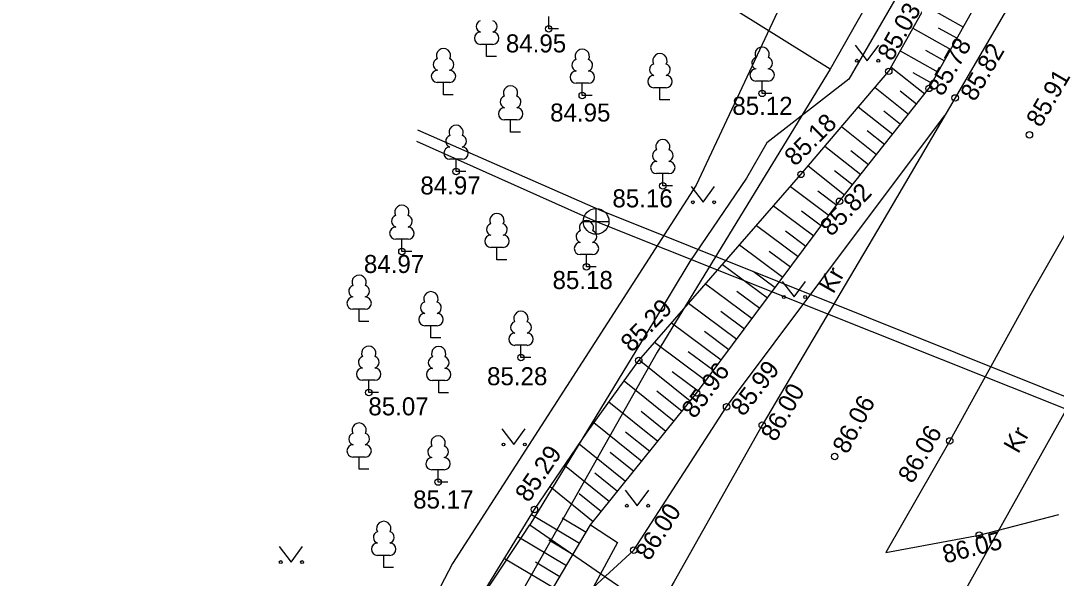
# Model space of a CAD drawing. Extents: x 648748 to 649126, y 6457789 to 6458252.
# Drawn here: x 648844.2 to 648884.43, y 6458119.64 to 6458141.27 of the extents above; entities that cross this region are included whole.
import ezdxf

# ---------------------------------------------------------------- set-up
doc = ezdxf.new("R2010")
doc.units = 0
for name, color, linetype in [('HALJASTUS', 7, 'Continuous'), ('KKAEV', 7, 'Continuous'), ('KORGUS-EH2000', 7, 'Continuous'), ('KTRASS', 7, 'Continuous'), ('PIIR', 7, 'Continuous'), ('PUU', 7, 'Continuous'), ('RELJEEF', 7, 'Continuous'), ('SITRASS', 7, 'Continuous'), ('TEE', 7, 'Continuous'), ('VTRASS', 7, 'Continuous')]:
    doc.layers.add(name, color=color, linetype=linetype)

msp = doc.modelspace()

# ---------------------------------------------------------------- linework, layer by layer
at = {"layer": 'HALJASTUS'}
for p, q in [((648876.62, 6458140.322), (648877.084, 6458139.716)), ((648877.084, 6458139.716), (648877.529, 6458140.322)), ((648870.245, 6458134.831), (648870.708, 6458134.225)), ((648870.708, 6458134.225), (648871.154, 6458134.831)), ((648873.781, 6458131.155), (648874.245, 6458130.549)), ((648874.245, 6458130.549), (648874.69, 6458131.155)), ((648862.892, 6458125.431), (648863.356, 6458124.825)), ((648863.356, 6458124.825), (648863.801, 6458125.431)), ((648867.685, 6458123.058), (648868.149, 6458122.451)), ((648868.149, 6458122.451), (648868.594, 6458123.058)), ((648854.237, 6458120.871), (648854.7, 6458120.264)), ((648854.7, 6458120.264), (648855.146, 6458120.871))]:
    msp.add_line(p, q, dxfattribs=at)
for centre in [(648876.683, 6458139.716), (648877.512, 6458139.716), (648870.307, 6458134.225), (648871.136, 6458134.225), (648873.844, 6458130.549), (648874.673, 6458130.549), (648862.955, 6458124.825), (648863.784, 6458124.825), (648867.748, 6458122.451), (648868.577, 6458122.451), (648854.299, 6458120.264), (648855.128, 6458120.264)]:
    msp.add_circle(centre, 0.055, dxfattribs=at)
at = {"layer": 'KKAEV'}
for p, q in [((648866.552, 6458132.983), (648866.552, 6458133.983)), ((648866.052, 6458133.483), (648867.052, 6458133.483))]:
    msp.add_line(p, q, dxfattribs=at)
msp.add_circle((648866.552, 6458133.483), 0.5, dxfattribs=at)
at = {"layer": 'KORGUS-EH2000'}
for centre in [(648864.71, 6458140.952), (648877.92, 6458139.306), (648879.482, 6458138.641), (648866.014, 6458138.367), (648873, 6458138.45), (648880.501, 6458138.274), (648883.385, 6458136.841), (648861.112, 6458135.416), (648874.51, 6458135.307), (648869.143, 6458134.861), (648876.009, 6458134.263), (648859.008, 6458132.315), (648866.176, 6458131.718), (648863.633, 6458128.199), (648868.207, 6458128.087), (648857.719, 6458126.844), (648870.456, 6458126.824), (648871.621, 6458126.287), (648873.007, 6458125.579), (648880.288, 6458124.965), (648875.819, 6458124.361), (648860.414, 6458123.369), (648864.155, 6458122.302), (648881.434, 6458121.312), (648868.014, 6458120.727)]:
    msp.add_circle(centre, 0.125, dxfattribs=at)
at = {"layer": 'KTRASS'}
for p, q in [((648859.569, 6458136.592), (648866.552, 6458133.483)), ((648866.552, 6458133.483), (648887.002, 6458125.324))]:
    msp.add_line(p, q, dxfattribs=at)
at = {"layer": 'PIIR'}
for p, q in [((648904.5, 6458190.31), (648875.65, 6458139.39)), ((648875.65, 6458139.39), (648850.168, 6458155.262)), ((648875.65, 6458139.39), (648868.92, 6458128.41)), ((648874.11, 6458107.05), (648886.69, 6458129.53)), ((648868.92, 6458128.41), (648793.25, 6457994.41))]:
    msp.add_line(p, q, dxfattribs=at)
at = {"layer": 'PUU'}
for p, q in [((648864.71, 6458140.952), (648864.71, 6458141.427)), ((648865.09, 6458140.952), (648864.71, 6458140.952)), ((648862.539, 6458140.351), (648862.059, 6458140.351)), ((648862.299, 6458139.876), (648862.299, 6458140.351)), ((648862.679, 6458139.876), (648862.299, 6458139.876)), ((648860.864, 6458138.872), (648860.384, 6458138.872)), ((648860.624, 6458138.397), (648860.624, 6458138.872)), ((648866.253, 6458138.842), (648865.774, 6458138.842)), ((648866.014, 6458138.367), (648866.014, 6458138.842)), ((648869.271, 6458138.671), (648868.791, 6458138.671)), ((648869.031, 6458138.196), (648869.031, 6458138.671)), ((648873.24, 6458138.925), (648872.76, 6458138.925)), ((648873, 6458138.45), (648873, 6458138.925)), ((648861.004, 6458138.397), (648860.624, 6458138.397)), ((648866.394, 6458138.367), (648866.014, 6458138.367)), ((648869.411, 6458138.196), (648869.031, 6458138.196)), ((648873.38, 6458138.45), (648873, 6458138.45)), ((648863.47, 6458137.419), (648862.99, 6458137.419)), ((648863.23, 6458136.944), (648863.23, 6458137.419)), ((648863.61, 6458136.944), (648863.23, 6458136.944)), ((648861.352, 6458135.891), (648860.872, 6458135.891)), ((648861.112, 6458135.416), (648861.112, 6458135.891)), ((648861.492, 6458135.416), (648861.112, 6458135.416)), ((648869.383, 6458135.336), (648868.903, 6458135.336)), ((648869.143, 6458134.861), (648869.143, 6458135.336)), ((648869.523, 6458134.861), (648869.143, 6458134.861)), ((648859.248, 6458132.79), (648858.768, 6458132.79)), ((648859.008, 6458132.315), (648859.008, 6458132.79)), ((648859.388, 6458132.315), (648859.008, 6458132.315)), ((648862.94, 6458132.472), (648862.46, 6458132.472)), ((648862.7, 6458131.997), (648862.7, 6458132.472)), ((648866.416, 6458132.193), (648865.936, 6458132.193)), ((648866.176, 6458131.718), (648866.176, 6458132.193)), ((648863.08, 6458131.997), (648862.7, 6458131.997)), ((648866.556, 6458131.718), (648866.176, 6458131.718)), ((648857.585, 6458130.076), (648857.105, 6458130.076)), ((648857.345, 6458129.601), (648857.345, 6458130.076)), ((648857.725, 6458129.601), (648857.345, 6458129.601)), ((648860.376, 6458129.435), (648859.896, 6458129.435)), ((648860.136, 6458128.96), (648860.136, 6458129.435)), ((648860.516, 6458128.96), (648860.136, 6458128.96)), ((648863.873, 6458128.674), (648863.393, 6458128.674)), ((648863.633, 6458128.199), (648863.633, 6458128.674)), ((648864.013, 6458128.199), (648863.633, 6458128.199)), ((648857.959, 6458127.319), (648857.479, 6458127.319)), ((648857.719, 6458126.844), (648857.719, 6458127.319)), ((648860.676, 6458127.306), (648860.196, 6458127.306)), ((648860.436, 6458126.831), (648860.436, 6458127.306)), ((648858.099, 6458126.844), (648857.719, 6458126.844)), ((648860.816, 6458126.831), (648860.436, 6458126.831)), ((648857.586, 6458124.34), (648857.106, 6458124.34)), ((648857.346, 6458123.865), (648857.346, 6458124.34)), ((648857.726, 6458123.865), (648857.346, 6458123.865)), ((648860.654, 6458123.844), (648860.174, 6458123.844)), ((648860.414, 6458123.369), (648860.414, 6458123.844)), ((648860.794, 6458123.369), (648860.414, 6458123.369)), ((648858.541, 6458120.525), (648858.061, 6458120.525)), ((648858.301, 6458120.05), (648858.301, 6458120.525)), ((648858.681, 6458120.05), (648858.301, 6458120.05))]:
    msp.add_line(p, q, dxfattribs=at)
for centre, radius, start, end in [((648862.129, 6458141.048), 0.233, 109.022, 253.142), ((648862.469, 6458141.048), 0.233, 286.851, 70.986), ((648862.062, 6458140.588), 0.238, 90.002, 269.395), ((648862.537, 6458140.588), 0.238, 270.605, 89.998), ((648873, 6458139.97), 0.277, 332.58, 207.42), ((648860.624, 6458139.917), 0.277, 332.58, 207.42), ((648866.014, 6458139.887), 0.277, 332.58, 207.42), ((648869.031, 6458139.716), 0.277, 332.58, 207.42), ((648872.83, 6458139.623), 0.233, 109.022, 253.142), ((648873.17, 6458139.623), 0.233, 286.851, 70.986), ((648860.454, 6458139.57), 0.233, 109.022, 253.142), ((648860.794, 6458139.57), 0.233, 286.851, 70.986), ((648865.844, 6458139.54), 0.233, 109.022, 253.142), ((648866.184, 6458139.54), 0.233, 286.851, 70.986), ((648868.861, 6458139.368), 0.233, 109.022, 253.142), ((648869.201, 6458139.368), 0.233, 286.851, 70.986), ((648860.386, 6458139.11), 0.238, 90.002, 269.395), ((648860.861, 6458139.11), 0.238, 270.605, 89.998), ((648865.776, 6458139.08), 0.238, 90.002, 269.395), ((648866.251, 6458139.08), 0.238, 270.605, 89.998), ((648868.794, 6458138.908), 0.238, 90.002, 269.395), ((648869.269, 6458138.908), 0.238, 270.605, 89.998), ((648872.763, 6458139.163), 0.238, 90.002, 269.395), ((648873.238, 6458139.163), 0.238, 270.605, 89.998), ((648863.23, 6458138.464), 0.277, 332.58, 207.42), ((648863.06, 6458138.117), 0.233, 109.022, 253.142), ((648863.4, 6458138.117), 0.233, 286.851, 70.986), ((648862.993, 6458137.657), 0.238, 90.002, 269.395), ((648863.468, 6458137.657), 0.238, 270.605, 89.998), ((648861.112, 6458136.936), 0.277, 332.58, 207.42), ((648860.942, 6458136.589), 0.233, 109.022, 253.142), ((648861.282, 6458136.589), 0.233, 286.851, 70.986), ((648869.143, 6458136.381), 0.277, 332.58, 207.42), ((648860.875, 6458136.129), 0.238, 90.002, 269.395), ((648861.35, 6458136.129), 0.238, 270.605, 89.998), ((648868.973, 6458136.033), 0.233, 109.022, 253.142), ((648869.313, 6458136.033), 0.233, 286.851, 70.986), ((648868.905, 6458135.573), 0.238, 90.002, 269.395), ((648869.38, 6458135.573), 0.238, 270.605, 89.998), ((648859.008, 6458133.835), 0.277, 332.58, 207.42), ((648862.7, 6458133.517), 0.277, 332.58, 207.42), ((648858.838, 6458133.487), 0.233, 109.022, 253.142), ((648859.178, 6458133.487), 0.233, 286.851, 70.986), ((648862.53, 6458133.17), 0.233, 109.022, 253.142), ((648862.87, 6458133.17), 0.233, 286.851, 70.986), ((648866.176, 6458133.238), 0.277, 332.58, 207.42), ((648858.77, 6458133.027), 0.238, 90.002, 269.395), ((648859.245, 6458133.027), 0.238, 270.605, 89.998), ((648866.006, 6458132.891), 0.233, 109.022, 253.142), ((648866.346, 6458132.891), 0.233, 286.851, 70.986), ((648862.462, 6458132.71), 0.238, 90.002, 269.395), ((648862.937, 6458132.71), 0.238, 270.605, 89.998), ((648865.939, 6458132.431), 0.238, 90.002, 269.395), ((648866.414, 6458132.431), 0.238, 270.605, 89.998), ((648857.345, 6458131.121), 0.277, 332.58, 207.42), ((648857.175, 6458130.773), 0.233, 109.022, 253.142), ((648857.515, 6458130.773), 0.233, 286.851, 70.986), ((648857.108, 6458130.313), 0.238, 90.002, 269.395), ((648857.583, 6458130.313), 0.238, 270.605, 89.998), ((648860.136, 6458130.48), 0.277, 332.58, 207.42), ((648859.966, 6458130.133), 0.233, 109.022, 253.142), ((648860.306, 6458130.133), 0.233, 286.851, 70.986), ((648859.898, 6458129.673), 0.238, 90.002, 269.395), ((648860.373, 6458129.673), 0.238, 270.605, 89.998), ((648863.633, 6458129.719), 0.277, 332.58, 207.42), ((648863.463, 6458129.371), 0.233, 109.022, 253.142), ((648863.803, 6458129.371), 0.233, 286.851, 70.986), ((648863.395, 6458128.911), 0.238, 90.002, 269.395), ((648863.87, 6458128.911), 0.238, 270.605, 89.998), ((648857.719, 6458128.364), 0.277, 332.58, 207.42), ((648860.436, 6458128.351), 0.277, 332.58, 207.42), ((648857.549, 6458128.016), 0.233, 109.022, 253.142), ((648857.889, 6458128.016), 0.233, 286.851, 70.986), ((648860.266, 6458128.004), 0.233, 109.022, 253.142), ((648860.606, 6458128.004), 0.233, 286.851, 70.986), ((648857.482, 6458127.556), 0.238, 90.002, 269.395), ((648857.957, 6458127.556), 0.238, 270.605, 89.998), ((648860.199, 6458127.544), 0.238, 90.002, 269.395), ((648860.674, 6458127.544), 0.238, 270.605, 89.998), ((648857.346, 6458125.385), 0.277, 332.58, 207.42), ((648857.176, 6458125.038), 0.233, 109.022, 253.142), ((648857.516, 6458125.038), 0.233, 286.851, 70.986), ((648860.414, 6458124.889), 0.277, 332.58, 207.42), ((648857.109, 6458124.578), 0.238, 90.002, 269.395), ((648857.584, 6458124.578), 0.238, 270.605, 89.998), ((648860.244, 6458124.541), 0.233, 109.022, 253.142), ((648860.584, 6458124.541), 0.233, 286.851, 70.986), ((648860.176, 6458124.081), 0.238, 90.002, 269.395), ((648860.651, 6458124.081), 0.238, 270.605, 89.998), ((648858.301, 6458121.57), 0.277, 332.58, 207.42), ((648858.131, 6458121.222), 0.233, 109.022, 253.142), ((648858.471, 6458121.222), 0.233, 286.851, 70.986), ((648858.064, 6458120.762), 0.238, 90.002, 269.395), ((648858.539, 6458120.762), 0.238, 270.605, 89.998)]:
    msp.add_arc(centre, radius, start, end, dxfattribs=at)
at = {"layer": 'RELJEEF'}
for p, q in [((648879.348, 6458141.848), (648880.819, 6458141.022)), ((648878.858, 6458140.976), (648880.329, 6458140.15)), ((648879.838, 6458140.999), (648880.574, 6458140.586)), ((648878.368, 6458140.104), (648879.84, 6458139.278)), ((648879.349, 6458140.127), (648880.084, 6458139.714)), ((648878.009, 6458139.465), (648879.315, 6458138.43)), ((648878.859, 6458139.255), (648879.595, 6458138.842)), ((648877.388, 6458138.682), (648878.693, 6458137.646)), ((648878.358, 6458138.55), (648879.004, 6458138.038)), ((648876.738, 6458137.921), (648878.072, 6458136.863)), ((648877.723, 6458137.778), (648878.382, 6458137.255)), ((648876.089, 6458137.159), (648877.45, 6458136.079)), ((648877.087, 6458137.006), (648877.761, 6458136.471)), ((648875.44, 6458136.398), (648876.829, 6458135.296)), ((648876.452, 6458136.233), (648877.139, 6458135.688)), ((648874.791, 6458135.636), (648876.207, 6458134.513)), ((648875.817, 6458135.461), (648876.518, 6458134.904)), ((648874.1, 6458134.838), (648875.602, 6458133.717)), ((648875.165, 6458134.667), (648875.901, 6458134.118)), ((648873.441, 6458134.082), (648875.003, 6458132.916)), ((648874.536, 6458133.888), (648875.302, 6458133.316)), ((648872.781, 6458133.327), (648874.405, 6458132.114)), ((648873.907, 6458133.11), (648874.704, 6458132.515)), ((648872.122, 6458132.571), (648873.807, 6458131.313)), ((648873.279, 6458132.331), (648874.106, 6458131.714)), ((648871.462, 6458131.816), (648873.209, 6458130.512)), ((648872.65, 6458131.553), (648873.508, 6458130.912)), ((648870.802, 6458131.06), (648872.61, 6458129.71)), ((648872.021, 6458130.775), (648872.909, 6458130.111)), ((648870.143, 6458130.305), (648872.012, 6458128.909)), ((648871.392, 6458129.996), (648872.311, 6458129.31)), ((648869.483, 6458129.549), (648871.414, 6458128.108)), ((648870.763, 6458129.218), (648871.713, 6458128.508)), ((648868.824, 6458128.794), (648870.816, 6458127.307)), ((648870.134, 6458128.439), (648871.115, 6458127.707)), ((648868.226, 6458128.109), (648870.206, 6458126.514)), ((648869.505, 6458127.661), (648870.516, 6458126.906)), ((648867.638, 6458127.298), (648869.579, 6458125.735)), ((648868.911, 6458126.914), (648869.892, 6458126.125)), ((648867.052, 6458126.486), (648868.951, 6458124.956)), ((648868.305, 6458126.119), (648869.265, 6458125.346)), ((648866.466, 6458125.674), (648868.324, 6458124.177)), ((648867.698, 6458125.323), (648868.638, 6458124.567)), ((648865.891, 6458124.853), (648867.697, 6458123.399)), ((648867.092, 6458124.528), (648868.011, 6458123.788)), ((648865.327, 6458124.023), (648867.07, 6458122.62)), ((648866.496, 6458123.724), (648867.384, 6458123.009)), ((648864.762, 6458123.194), (648866.443, 6458121.841)), ((648865.9, 6458122.919), (648866.756, 6458122.23)), ((648864.036, 6458122.108), (648865.913, 6458120.994)), ((648865.238, 6458121.976), (648866.168, 6458121.424)), ((648863.511, 6458121.256), (648865.403, 6458120.134)), ((648864.716, 6458121.123), (648865.658, 6458120.564)), ((648862.987, 6458120.405), (648864.893, 6458119.274)), ((648864.199, 6458120.267), (648865.148, 6458119.704))]:
    msp.add_line(p, q, dxfattribs=at)
for points in [[(648843.02, 6458077.359), (648843.42, 6458078.532), (648845.59, 6458084.371), (648850.065, 6458093.899), (648854.008, 6458102.777), (648855.882, 6458106.866), (648857.274, 6458110.27), (648859.944, 6458115.461), (648864.155, 6458122.302), (648866.203, 6458125.31), (648868.207, 6458128.087), (648874.51, 6458135.307), (648877.92, 6458139.306), (648882.178, 6458146.884)], [(648844.206, 6458076.8), (648844.687, 6458077.74), (648847.597, 6458083.411), (648851.411, 6458092.995), (648855.57, 6458101.941), (648857.624, 6458105.762), (648858.713, 6458108.175), (648859.587, 6458110.038), (648862.771, 6458115.697), (648866.339, 6458121.712), (648870.456, 6458126.824), (648876.009, 6458134.263), (648879.482, 6458138.641), (648881.386, 6458142.032), (648883.388, 6458145.778), (648883.683, 6458146.633)]]:
    msp.add_lwpolyline(points, dxfattribs=at)
at = {"layer": 'SITRASS'}
for points in [[(648929.925, 6458240.085), (648929.233, 6458238.833), (648926.729, 6458233.327), (648923.21, 6458225.506), (648918.966, 6458215.361), (648917.027, 6458210.342), (648911.341, 6458199.533), (648902.157, 6458183.584), (648896.992, 6458174.764), (648890.118, 6458163.377), (648888.523, 6458160), (648880.878, 6458146.779), (648876.372, 6458138.998), (648873.186, 6458136.533), (648872.398, 6458135.159), (648870.194, 6458131.921), (648868.778, 6458129.583), (648863.975, 6458121.708)], [(648896.343, 6458186.017), (648897.439, 6458185.494), (648891.994, 6458176.157), (648887.134, 6458166.562), (648880.865, 6458155.928), (648874.577, 6458143.726), (648870.442, 6458134.893), (648860.973, 6458120.207), (648854.483, 6458107.787), (648851.762, 6458098.853), (648850.917, 6458095.378), (648847.878, 6458090.581), (648844.467, 6458087.013), (648842.522, 6458085.072), (648840.521, 6458082.239)], [(648863.975, 6458121.708), (648868.963, 6458118.276), (648873.908, 6458114.787), (648879.921, 6458111.046), (648881.11, 6458110.63), (648883.242, 6458110.955), (648895.055, 6458116.596), (648901.713, 6458119.167), (648915.597, 6458124.69), (648933.55, 6458131.654), (648947.17, 6458136.394), (648958.488, 6458140.137), (648967.592, 6458140.769)], [(648840.642, 6458076.21), (648839.879, 6458076.526), (648839.144, 6458077.498), (648844.394, 6458087.729), (648849.387, 6458096.156), (648854.312, 6458104.237), (648857.262, 6458110.389), (648861.217, 6458117.552), (648863.683, 6458121.25), (648863.975, 6458121.708)]]:
    msp.add_lwpolyline(points, dxfattribs=at)
at = {"layer": 'TEE'}
for points in [[(648898.467, 6458156.964), (648883.402, 6458130.595), (648880.288, 6458124.965), (648877.804, 6458120.639), (648881.434, 6458121.312), (648884.526, 6458122.113)], [(648886.897, 6458149.241), (648880.501, 6458138.274), (648877.651, 6458133.428), (648873.007, 6458125.579), (648869.584, 6458119.515), (648862.268, 6458107.116), (648858.84, 6458100.574), (648853.992, 6458092.302), (648848.947, 6458082.671), (648845.759, 6458077.188), (648844.3, 6458074.59)], [(648866.432, 6458119.274), (648868.014, 6458120.727), (648871.621, 6458126.287), (648877.176, 6458133.694), (648880.102, 6458137.595)], [(648860.41, 6458108.819), (648859.531, 6458107.727), (648858.713, 6458108.175), (648859.587, 6458110.038), (648862.771, 6458115.697), (648866.339, 6458121.712), (648867.381, 6458121.025), (648866.432, 6458119.274)]]:
    msp.add_lwpolyline(points, dxfattribs=at)
at = {"layer": 'VTRASS'}
msp.add_lwpolyline([(648859.612, 6458137.039), (648866.748, 6458133.902), (648887.357, 6458125.656), (648899.553, 6458111.732), (648928.544, 6458121.558), (648956.932, 6458132.595), (648957.558, 6458132.798), (648975.434, 6458138.594), (648975.797, 6458138.798), (648976.302, 6458139.082)], dxfattribs=at)

# ---------------------------------------------------------------- texts
at = {"layer": 'KORGUS-EH2000'}
for s, rotation, p in [('85.03', 60.668, (648878.046, 6458139.662)), ('85.78', 60.6928, (648880.008, 6458138.302)), ('85.82', 59.7476, (648881.262, 6458138.098)), ('85.91', 59.7476, (648883.819, 6458137.091)), ('85.18', 44.5787, (648874.281, 6458135.59)), ('85.82', 46.0675, (648875.687, 6458132.866)), ('85.29', 46.0649, (648867.936, 6458128.37)), ('85.96', 53.427, (648870.377, 6458125.791)), ('85.99', 52.0503, (648872.273, 6458125.881)), ('86.00', 60.3537, (648873.52, 6458124.894)), ('86.06', 61.9984, (648876.312, 6458124.418)), ('86.06', 60.1394, (648878.844, 6458123.274)), ('85.29', 55.8044, (648863.932, 6458122.54)), ('86.00', 57.3647, (648868.62, 6458120.275)), ('86.05', 14.5247, (648880.111, 6458120.206))]:
    msp.add_text(s, height=0.7, rotation=rotation, dxfattribs=at).set_placement(p)
for s, p in [('84.95', (648863.046, 6458140.039)), ('85.12', (648871.843, 6458137.617)), ('84.95', (648864.766, 6458137.356)), ('84.97', (648859.725, 6458134.527)), ('85.16', (648867.185, 6458134.027)), ('84.97', (648857.531, 6458131.481)), ('85.18', (648864.859, 6458130.858)), ('85.28', (648862.316, 6458127.125)), ('85.07', (648857.705, 6458125.957)), ('85.17', (648859.445, 6458122.342))]:
    msp.add_text(s, height=0.7, dxfattribs=at).set_placement(p)
at = {"layer": 'TEE'}
for rotation, p in [(60.2687, (648875.764, 6458130.639)), (60.3302, (648882.949, 6458124.438))]:
    msp.add_text('Kr', height=0.7, rotation=rotation, dxfattribs=at).set_placement(p)

doc.saveas('drawing.dxf')
